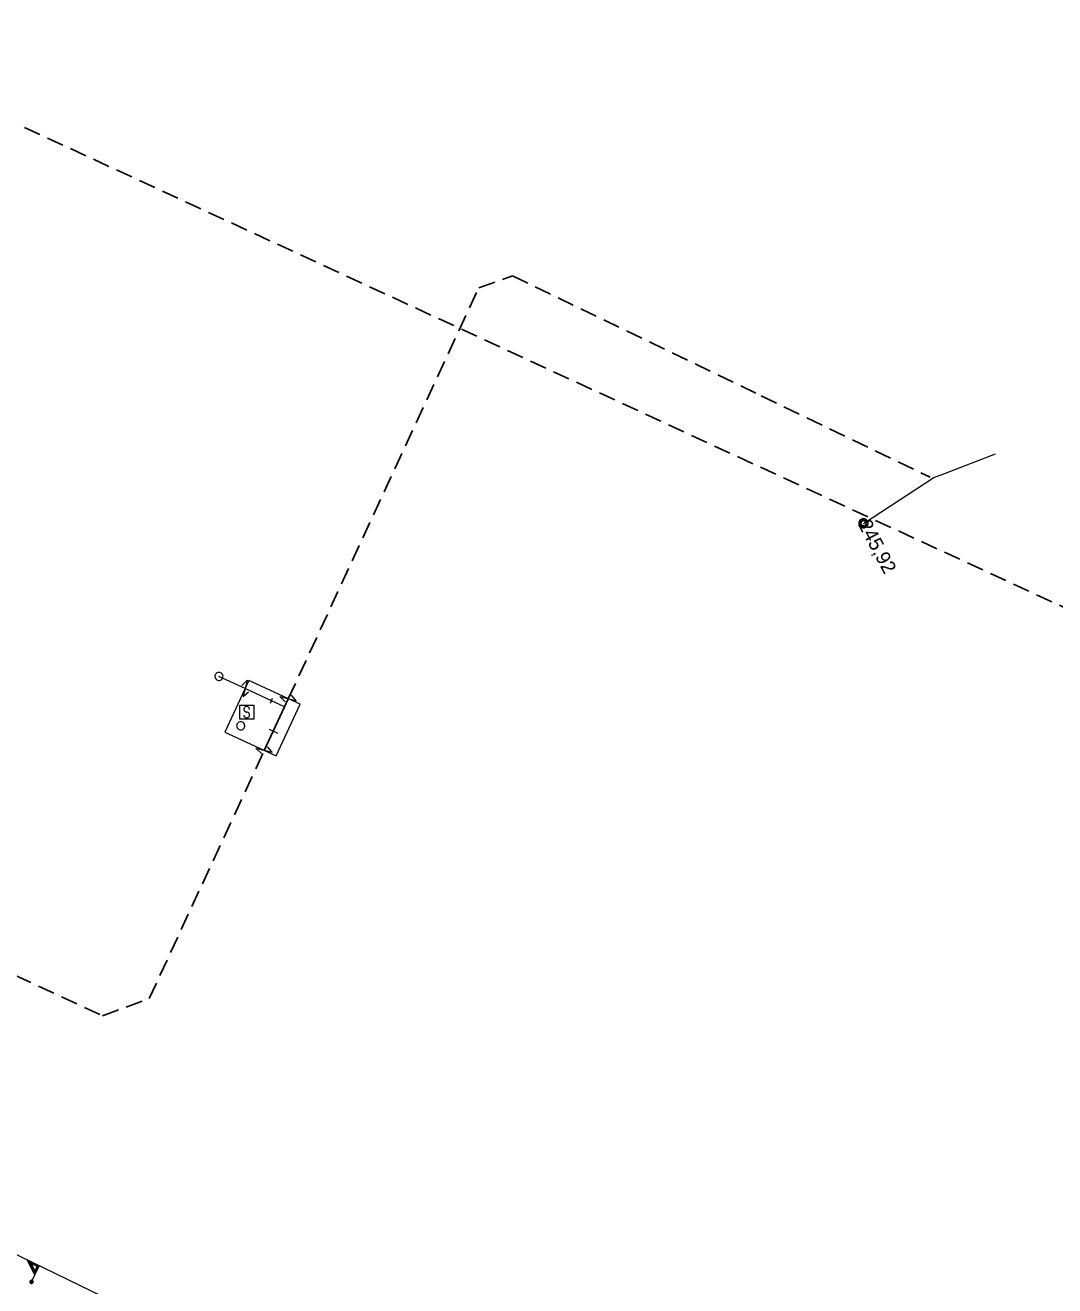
# Model space of a CAD drawing. Extents: x -735085 to -733500, y -1044153 to -1043402.
# Drawn here: x -734650.3 to -734591.8, y -1043643.2 to -1043571.5 of the extents above; entities that cross this region are included whole.
import ezdxf

# ---------------------------------------------------------------- set-up
doc = ezdxf.new("R2010")
doc.units = 0
doc.header["$LTSCALE"] = 0.32
doc.linetypes.add('DOT_DASHED', pattern=[7.7, 5, -1.2, 0.3, -1.2])
doc.linetypes.add('MEDIUM_DASHED', pattern=[4.5, 3, -1.5])
doc.layers.add('16', color=7, linetype='Continuous')
for name, color, linetype, lineweight in [('18', 7, 'Continuous', 13), ('20', 7, 'Continuous', 13), ('49', 7, 'Continuous', 13), ('63', 7, 'MEDIUM_DASHED', 25), ('8', 7, 'Continuous', 13)]:
    doc.layers.add(name, color=color, linetype=linetype, lineweight=lineweight)

msp = doc.modelspace()

# ---------------------------------------------------------------- linework, layer by layer
at = {"layer": '18'}
for points in [[(-734602.372, -1043599.838), (-734602.378, -1043599.782), (-734602.395, -1043599.729), (-734602.424, -1043599.68), (-734602.462, -1043599.639), (-734602.508, -1043599.607), (-734602.56, -1043599.585), (-734602.615, -1043599.574), (-734602.671, -1043599.576), (-734602.726, -1043599.589), (-734602.777, -1043599.614), (-734602.821, -1043599.649), (-734602.857, -1043599.692), (-734602.882, -1043599.742), (-734602.897, -1043599.797), (-734602.9, -1043599.853), (-734602.891, -1043599.908), (-734602.87, -1043599.961), (-734602.839, -1043600.007), (-734602.799, -1043600.046), (-734602.751, -1043600.076), (-734602.698, -1043600.095), (-734602.642, -1043600.102), (-734602.586, -1043600.098), (-734602.532, -1043600.081), (-734602.483, -1043600.054), (-734602.441, -1043600.016), (-734602.408, -1043599.971), (-734602.385, -1043599.92), (-734602.373, -1043599.865)], [(-734602.431, -1043599.841), (-734602.437, -1043599.792), (-734602.455, -1043599.746), (-734602.483, -1043599.705), (-734602.52, -1043599.672), (-734602.564, -1043599.65), (-734602.612, -1043599.638), (-734602.661, -1043599.638), (-734602.709, -1043599.65), (-734602.753, -1043599.673), (-734602.79, -1043599.706), (-734602.818, -1043599.747), (-734602.835, -1043599.794), (-734602.841, -1043599.843), (-734602.834, -1043599.892), (-734602.816, -1043599.938), (-734602.788, -1043599.978), (-734602.751, -1043600.011), (-734602.707, -1043600.033), (-734602.658, -1043600.045), (-734602.609, -1043600.044), (-734602.561, -1043600.032), (-734602.518, -1043600.008), (-734602.481, -1043599.975), (-734602.453, -1043599.934), (-734602.437, -1043599.887)], [(-734602.49, -1043599.845), (-734602.496, -1043599.803), (-734602.513, -1043599.765), (-734602.541, -1043599.734), (-734602.576, -1043599.711), (-734602.616, -1043599.7), (-734602.658, -1043599.7), (-734602.698, -1043599.712), (-734602.733, -1043599.735), (-734602.76, -1043599.767), (-734602.777, -1043599.805), (-734602.782, -1043599.846), (-734602.776, -1043599.888), (-734602.758, -1043599.925), (-734602.73, -1043599.957), (-734602.694, -1043599.979), (-734602.654, -1043599.99), (-734602.612, -1043599.989), (-734602.572, -1043599.976), (-734602.538, -1043599.953), (-734602.511, -1043599.92), (-734602.495, -1043599.882)], [(-734649.999, -1043642.903), (-734650.008, -1043642.936), (-734650.005, -1043642.969), (-734649.991, -1043642.999), (-734649.967, -1043643.022), (-734649.936, -1043643.036), (-734649.903, -1043643.038), (-734649.87, -1043643.028), (-734649.844, -1043643.007), (-734649.826, -1043642.979), (-734649.82, -1043642.946), (-734649.825, -1043642.913), (-734649.841, -1043642.884), (-734649.867, -1043642.863), (-734649.898, -1043642.851), (-734649.932, -1043642.851), (-734649.963, -1043642.864), (-734649.989, -1043642.886)], [(-734649.974, -1043642.913), (-734649.981, -1043642.941), (-734649.975, -1043642.969), (-734649.96, -1043642.992), (-734649.935, -1043643.007), (-734649.907, -1043643.01), (-734649.88, -1043643.002), (-734649.859, -1043642.983), (-734649.847, -1043642.957), (-734649.848, -1043642.929), (-734649.859, -1043642.903), (-734649.881, -1043642.884), (-734649.907, -1043642.876), (-734649.935, -1043642.88), (-734649.96, -1043642.894)]]:
    msp.add_lwpolyline(points, close=True, dxfattribs=at)
for points in [[(-734649.954, -1043643.029), (-734649.478, -1043642.043), (-734650.172, -1043641.708), (-734649.73, -1043642.564)], [(-734649.724, -1043642.435), (-734649.543, -1043642.06), (-734650.052, -1043641.814), (-734649.725, -1043642.436)], [(-734649.73, -1043642.339), (-734649.603, -1043642.076), (-734649.937, -1043641.915), (-734649.729, -1043642.34)]]:
    msp.add_lwpolyline(points, dxfattribs=at)
at = {"layer": '20'}
msp.add_line((-734623.989, -1043654.36), (-734654.699, -1043639.52), dxfattribs=at)
msp.add_line((-734623.989, -1043654.36), (-734654.699, -1043639.52), dxfattribs=at)
at = {"layer": '49'}
msp.add_lwpolyline([(-734602.636, -1043599.851), (-734598.629, -1043597.24), (-734597.98, -1043596.99), (-734595.127, -1043595.894)], dxfattribs=at)
msp.add_lwpolyline([(-734602.636, -1043599.851), (-734598.629, -1043597.24), (-734597.98, -1043596.99), (-734595.127, -1043595.894)], dxfattribs=at)
at = {"layer": '63'}
msp.add_lwpolyline([(-734796.022, -1043808.279), (-734957.658, -1043641.023), (-734957.66, -1043641.021), (-735032.487, -1043496.398), (-735032.488, -1043496.396), (-735032.488, -1043496.394), (-735032.488, -1043496.393), (-735032.488, -1043496.391), (-735014.686, -1043433.916), (-735014.686, -1043433.914), (-735014.685, -1043433.913), (-735014.683, -1043433.911), (-735014.682, -1043433.91), (-735014.68, -1043433.909), (-735014.678, -1043433.909), (-735014.676, -1043433.909), (-734957.569, -1043435.5), (-734957.567, -1043435.5), (-734957.565, -1043435.501), (-734250.468, -1043761.931)], dxfattribs=at)
at = {"layer": '8'}
for p, q in [((-734637.776, -1043609.233), (-734639.266, -1043608.549)), ((-734636.34, -1043610.052), (-734636.213, -1043609.776)), ((-734636.415, -1043611.54), (-734635.946, -1043611.758))]:
    msp.add_line(p, q, dxfattribs=at)
at = {"layer": '8', "linetype": 'DOT_DASHED', "lineweight": 25}
msp.add_line((-734636.686, -1043612.742), (-734636.18, -1043611.65), dxfattribs=at)
at = {"layer": '8', "linetype": 'MEDIUM_DASHED', "lineweight": 25}
for points in [[(-734635.326, -1043609.807), (-734624.5, -1043586.451), (-734622.585, -1043585.778), (-734608.451, -1043592.594), (-734598.85, -1043597.22)], [(-734683.5, -1043610.41), (-734645.881, -1043627.826), (-734643.226, -1043626.851), (-734636.686, -1043612.742)]]:
    msp.add_lwpolyline(points, dxfattribs=at)
at = {"layer": '8'}
for points in [[(-734639.051, -1043608.635), (-734639.035, -1043608.586), (-734639.03, -1043608.533), (-734639.038, -1043608.481), (-734639.057, -1043608.431), (-734639.086, -1043608.388), (-734639.125, -1043608.353), (-734639.17, -1043608.327), (-734639.22, -1043608.311), (-734639.273, -1043608.308), (-734639.325, -1043608.317), (-734639.373, -1043608.338), (-734639.416, -1043608.368), (-734639.451, -1043608.408), (-734639.475, -1043608.454), (-734639.49, -1043608.504), (-734639.491, -1043608.557), (-734639.481, -1043608.608), (-734639.459, -1043608.657), (-734639.428, -1043608.698), (-734639.387, -1043608.732), (-734639.341, -1043608.755), (-734639.289, -1043608.768), (-734639.237, -1043608.768), (-734639.185, -1043608.757), (-734639.138, -1043608.734), (-734639.097, -1043608.701), (-734639.065, -1043608.66)], [(-734638.923, -1043611.704), (-734636.006, -1043613.058), (-734634.644, -1043610.123), (-734637.561, -1043608.769)], [(-734638.078, -1043610.165), (-734637.289, -1043610.165), (-734637.289, -1043610.965), (-734638.078, -1043610.965)], [(-734637.798, -1043611.348), (-734637.804, -1043611.296), (-734637.821, -1043611.246), (-734637.85, -1043611.202), (-734637.888, -1043611.165), (-734637.933, -1043611.138), (-734637.983, -1043611.122), (-734638.035, -1043611.117), (-734638.087, -1043611.124), (-734638.136, -1043611.143), (-734638.179, -1043611.173), (-734638.215, -1043611.212), (-734638.241, -1043611.257), (-734638.255, -1043611.308), (-734638.259, -1043611.36), (-734638.25, -1043611.412), (-734638.23, -1043611.46), (-734638.2, -1043611.503), (-734638.16, -1043611.538), (-734638.114, -1043611.562), (-734638.063, -1043611.576), (-734638.011, -1043611.578), (-734637.959, -1043611.568), (-734637.911, -1043611.546), (-734637.869, -1043611.514), (-734637.836, -1043611.474), (-734637.812, -1043611.427), (-734637.799, -1043611.376)]]:
    msp.add_lwpolyline(points, close=True, dxfattribs=at)
for points in [[(-734637.958, -1043609.065), (-734637.654, -1043608.745), (-734637.887, -1043609.682), (-734637.584, -1043609.412)], [(-734635.493, -1043609.988), (-734635.812, -1043609.682), (-734634.876, -1043609.919), (-734635.145, -1043609.614)], [(-734637.852, -1043610.748), (-734637.842, -1043610.791), (-734637.82, -1043610.83), (-734637.789, -1043610.861), (-734637.75, -1043610.882), (-734637.708, -1043610.893), (-734637.664, -1043610.891), (-734637.622, -1043610.878), (-734637.585, -1043610.854), (-734637.556, -1043610.821), (-734637.537, -1043610.781), (-734637.529, -1043610.738), (-734637.532, -1043610.694), (-734637.549, -1043610.653), (-734637.575, -1043610.618), (-734637.61, -1043610.591), (-734637.651, -1043610.574), (-734637.676, -1043610.569)], [(-734637.529, -1043610.411), (-734637.534, -1043610.368), (-734637.551, -1043610.327), (-734637.578, -1043610.293), (-734637.615, -1043610.267), (-734637.656, -1043610.252), (-734637.699, -1043610.249), (-734637.742, -1043610.257), (-734637.781, -1043610.277), (-734637.814, -1043610.306), (-734637.837, -1043610.344), (-734637.848, -1043610.386), (-734637.85, -1043610.429), (-734637.838, -1043610.472), (-734637.816, -1043610.509), (-734637.784, -1043610.54), (-734637.745, -1043610.56), (-734637.703, -1043610.569), (-734637.676, -1043610.569)], [(-734636.853, -1043612.923), (-734637.172, -1043612.617), (-734636.236, -1043612.854), (-734636.505, -1043612.549)]]:
    msp.add_lwpolyline(points, dxfattribs=at)
at = {"layer": '8', "linetype": 'DOT_DASHED'}
msp.add_lwpolyline([(-734635.537, -1043610.262), (-734636.28, -1043609.92), (-734637.776, -1043609.233)], dxfattribs=at)
at = {"layer": '8', "linetype": 'DOT_DASHED', "lineweight": 25}
msp.add_lwpolyline([(-734636.18, -1043611.65), (-734635.537, -1043610.262), (-734635.326, -1043609.807)], dxfattribs=at)

# ---------------------------------------------------------------- texts
at = {"layer": '16'}
msp.add_text('245,92', height=0.8, rotation=298, dxfattribs=at).set_placement((-734602.969, -1043599.892))

doc.saveas('drawing.dxf')
